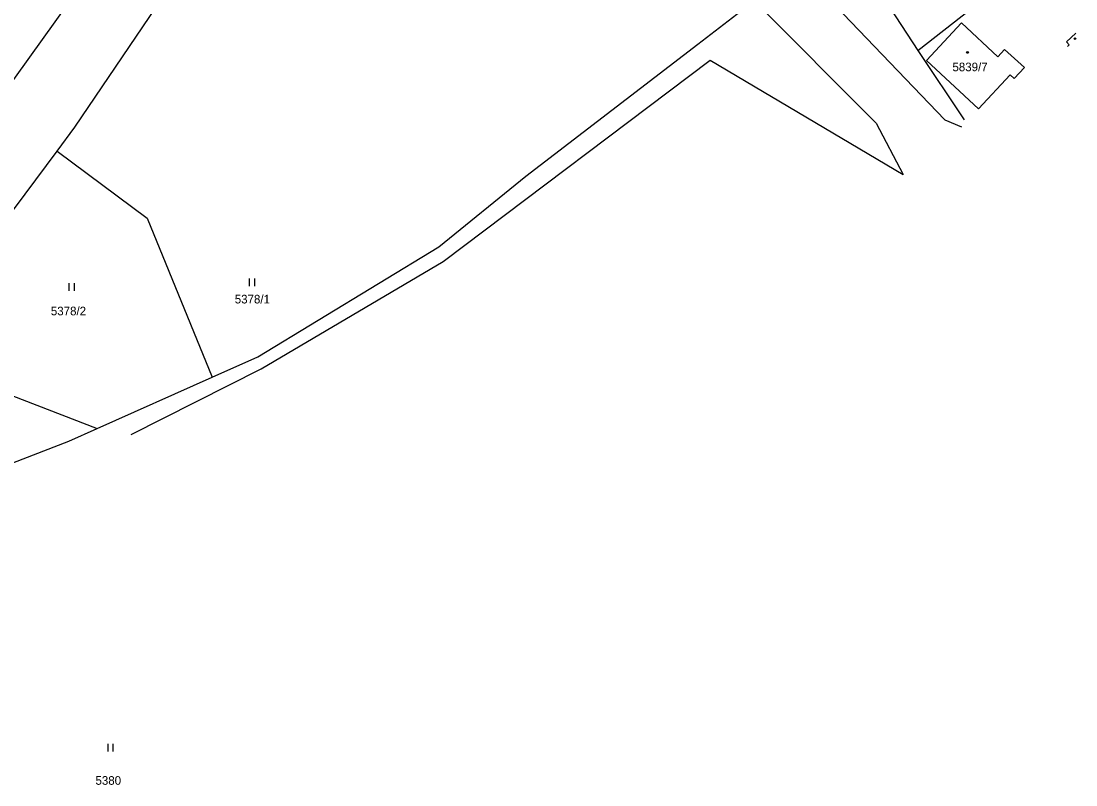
# Model space of a CAD drawing. Extents: x -717507 to -715515, y -957700 to -954941.
# Drawn here: x -715976.7 to -715768.6, y -955625.7 to -955475.1 of the extents above; entities that cross this region are included whole.
import ezdxf

# ---------------------------------------------------------------- set-up
doc = ezdxf.new("R2010")
doc.units = 0
for name, color, linetype in [('Hranice parcel', 7, 'Continuous'), ('Parcelní čísla', 7, 'Continuous'), ('Značky budov', 7, 'Continuous'), ('Značky kultur', 7, 'Continuous')]:
    doc.layers.add(name, color=color, linetype=linetype)

msp = doc.modelspace()

# ---------------------------------------------------------------- linework, layer by layer
at = {"layer": 'Hranice parcel'}
for points in [[(-715966.04, -955495.98), (-715913.69, -955418.64)], [(-715980.61, -955490.06), (-715936.99, -955429.22)], [(-715811.97, -955462.17), (-715799.84, -955480.85)], [(-715823.82, -955463.87), (-715794.5, -955494.51)], [(-715799.84, -955480.85), (-715779.3, -955464.75)], [(-715843.19, -955479.58), (-715832.1, -955471.05)], [(-715832.1, -955471.05), (-715808.03, -955495.19)], [(-715798.1, -955482.86), (-715791.18, -955475.4)], [(-715791.18, -955475.4), (-715784.06, -955482.1)], [(-715770.48, -955479.18), (-715768.67, -955477.43)], [(-715877.11, -955505.66), (-715843.19, -955479.58)], [(-715770.48, -955479.18), (-715769.95, -955479.72)], [(-715770.32, -955480.08), (-715769.95, -955479.72)], [(-715799.84, -955480.85), (-715790.7, -955494.53)], [(-715784.06, -955482.1), (-715782.73, -955480.64)], [(-715782.73, -955480.64), (-715778.8, -955484.22)], [(-715893.46, -955522.44), (-715840.75, -955482.74)], [(-715840.75, -955482.74), (-715802.7, -955505.28)], [(-715798.1, -955482.86), (-715787.86, -955492.37)], [(-715780.83, -955486.41), (-715778.8, -955484.22)], [(-715787.86, -955492.37), (-715781.64, -955485.66)], [(-715781.64, -955485.66), (-715780.83, -955486.41)], [(-715794.5, -955494.51), (-715791.2, -955495.94)], [(-715969.56, -955500.7), (-715966.04, -955495.98)], [(-715808.03, -955495.19), (-715802.7, -955505.28)], [(-715999.46, -955540.82), (-715969.56, -955500.7)], [(-715969.56, -955500.7), (-715951.79, -955513.92)], [(-715894.28, -955519.55), (-715877.11, -955505.66)], [(-715951.79, -955513.92), (-715938.97, -955545.28)], [(-715929.99, -955541.28), (-715894.28, -955519.55)], [(-715929.32, -955543.65), (-715893.46, -955522.44)], [(-715999.46, -955540.82), (-715961.64, -955555.4)], [(-715938.97, -955545.28), (-715929.99, -955541.28)], [(-715954.95, -955556.56), (-715929.32, -955543.65)], [(-715961.64, -955555.4), (-715938.97, -955545.28)], [(-715967.26, -955557.9), (-715961.64, -955555.4)], [(-716028.66, -955581.62), (-715967.26, -955557.9)]]:
    msp.add_lwpolyline(points, dxfattribs=at)
at = {"layer": 'Značky budov'}
for centre in [(-715768.82, -955478.52), (-715790.02, -955481.24)]:
    msp.add_circle(centre, 0.175, dxfattribs=at)
at = {"layer": 'Značky kultur'}
for points in [[(-715931.63, -955527.3), (-715931.63, -955525.8)], [(-715930.59, -955527.3), (-715930.59, -955525.8)], [(-715967.2, -955528.27), (-715967.2, -955526.77)], [(-715966.16, -955528.27), (-715966.16, -955526.77)], [(-715959.52, -955619.07), (-715959.52, -955617.57)], [(-715958.48, -955619.07), (-715958.48, -955617.57)]]:
    msp.add_lwpolyline(points, dxfattribs=at)

# ---------------------------------------------------------------- texts
at = {"layer": 'Parcelní čísla'}
for s, p in [('5839/7', (-715793, -955484.95)), ('5378/1', (-715934.53, -955530.74)), ('5378/2', (-715970.8, -955533.08)), ('5380', (-715962, -955625.66))]:
    msp.add_text(s, height=1.7, dxfattribs=at).set_placement(p)

doc.saveas('drawing.dxf')
